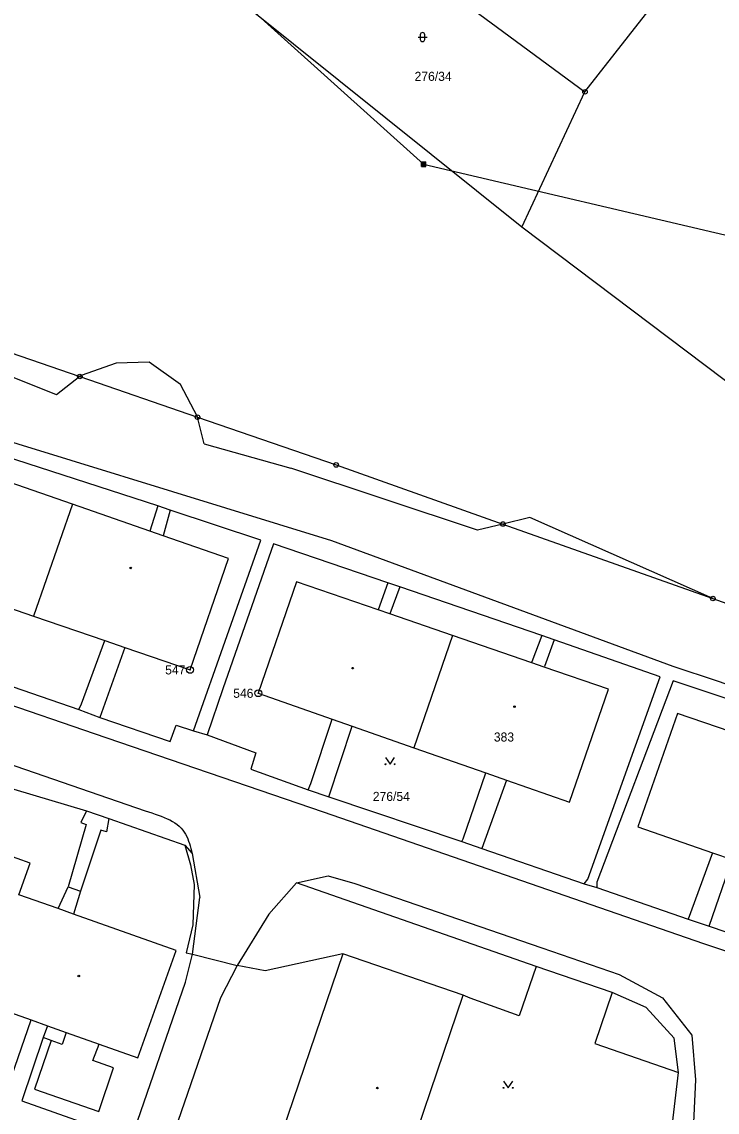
# Model space of a CAD drawing. Extents: x -745926 to -742978, y -968282 to -965689.
# Drawn here: x -744726.5 to -744649.7, y -967027 to -966906.6 of the extents above; entities that cross this region are included whole.
import ezdxf

# ---------------------------------------------------------------- set-up
doc = ezdxf.new("R2010")
doc.units = 0
for name, color, linetype in [('Hranice parcel', 7, 'Continuous'), ('Parcelní čísla', 7, 'Continuous'), ('Poz předměty', 7, 'Continuous'), ('Vnitřní kresba', 7, 'Continuous'), ('Značky bodu BP', 7, 'Continuous'), ('Značky budov', 7, 'Continuous'), ('Značky kultur', 7, 'Continuous')]:
    doc.layers.add(name, color=color, linetype=linetype)

msp = doc.modelspace()

# ---------------------------------------------------------------- linework, layer by layer
at = {"layer": 'Hranice parcel'}
for p, q in [((-744664.34, -966914.34), (-744608.93, -966843.39)), ((-744671.3, -966929.27), (-744664.34, -966914.34)), ((-744635.36, -966956.43), (-744671.3, -966929.27)), ((-744707.55, -966984.87), (-744706.03, -966985.33)), ((-744664.43, -967001.78), (-744663.03, -967002.19)), ((-744707.68, -967009.55), (-744702.72, -967010.81))]:
    msp.add_line(p, q, dxfattribs=at)
for points in [[(-744627.78, -966987.01), (-744649.71, -966979.39), (-744654.61, -966977.79), (-744692.27, -966963.9), (-744738.66, -966949.62), (-744739.71, -966948.97), (-744740.38, -966948.96), (-744778.84, -966930.46), (-744815.82, -966899.53), (-744818.58, -966883.89), (-744822.45, -966860.57), (-744822.45, -966858.85), (-744822.42, -966856.77), (-744822.4, -966854.94), (-744822.37, -966853.08), (-744822.37, -966851.59), (-744822.35, -966814.99), (-744823.48, -966815.03), (-744822.59, -966803.93), (-744824.77, -966768.68), (-744832.65, -966757.45)], [(-744671.3, -966929.27), (-744781.98, -966840.55), (-744773.37, -966830.03)], [(-744773.37, -966830.03), (-744770.39, -966832.47), (-744703.2, -966887.58), (-744695.37, -966891.46), (-744664.34, -966914.34)], [(-744812.79, -966854.17), (-744813.4, -966862.64), (-744813.73, -966867.2), (-744808, -966902.66), (-744776.73, -966926.26), (-744745.23, -966937.12), (-744720.11, -966945.77), (-744707.11, -966950.26), (-744691.81, -966955.53), (-744673.4, -966962.06), (-744650.22, -966970.28), (-744647.24, -966971.34)], [(-744707.55, -966984.87), (-744700.13, -966963.82), (-744710.14, -966960.53), (-744711.51, -966960.06), (-744727.15, -966954.96), (-744728.44, -966954.54), (-744739.28, -966950.98), (-744745.85, -966967), (-744748.26, -966972.98)], [(-744732.08, -966969.87), (-744725.21, -966972.23), (-744717.35, -966974.93), (-744715.13, -966975.69), (-744707.94, -966978.16), (-744703.71, -966965.87), (-744710.92, -966963.35), (-744712.38, -966962.84), (-744720.91, -966959.86), (-744727.9, -966957.42), (-744729.3, -966956.93), (-744738.11, -966953.85), (-744742.47, -966966.3), (-744734.37, -966969.08), (-744732.08, -966969.87)], [(-744664.43, -967001.78), (-744664.04, -967001.28), (-744656.03, -966978.91), (-744667.73, -966974.83), (-744669.12, -966974.37), (-744684.78, -966968.98), (-744686.09, -966968.53), (-744698.73, -966964.26), (-744704.32, -966980.26), (-744706.03, -966985.33)], [(-744700.4, -966980.74), (-744692.25, -966983.59), (-744690.05, -966984.36), (-744683.22, -966986.75), (-744675.28, -966989.54), (-744672.99, -966990.34), (-744666.04, -966992.77), (-744661.74, -966980.29), (-744668.84, -966977.85), (-744670.22, -966977.37), (-744678.96, -966974.36), (-744685.89, -966971.98), (-744687.16, -966971.54), (-744696.18, -966968.43), (-744700.4, -966980.74)], [(-744784.3, -966971.12), (-744752.54, -966982.26), (-744750.13, -966983.09), (-744736.11, -966988.32), (-744727.4, -966991.33), (-744719.35, -966993.73), (-744716.91, -966994.58), (-744708.53, -966997.5), (-744707.88, -966999.67), (-744707.48, -967001.85), (-744707.64, -967006.3), (-744708.35, -967009.41), (-744707.68, -967009.55)], [(-744748.26, -966972.98), (-744737.18, -966976.65), (-744734.84, -966977.5), (-744720.2, -966982.53), (-744717.89, -966983.4), (-744710.13, -966986.07), (-744709.48, -966984.27), (-744707.55, -966984.87)], [(-744624.63, -966989.55), (-744625.82, -966989.13), (-744627.17, -966988.69), (-744642.96, -966983.23), (-744644.23, -966982.84), (-744654.6, -966979.36), (-744663.03, -967001.61), (-744663.03, -967002.19)], [(-744641.26, -967001.49), (-744633.32, -967004.25), (-744631.15, -967005.01), (-744624.08, -967007.47), (-744619.61, -966994.77), (-744626.9, -966992.28), (-744628.31, -966991.8), (-744636.87, -966988.88), (-744643.88, -966986.49), (-744645.31, -966986), (-744654.14, -966982.99), (-744658.49, -966995.48), (-744650.28, -966998.34), (-744648.11, -966999.1), (-744641.26, -967001.49)], [(-744706.03, -966985.33), (-744700.69, -966987.33), (-744701.21, -966989.11), (-744694.89, -966991.39), (-744692.6, -966992.17), (-744677.94, -966997.1), (-744675.71, -966997.87), (-744664.43, -967001.78)], [(-744720.79, -967005.12), (-744722.5, -967004.51), (-744726.82, -967002.98), (-744725.58, -966999.49), (-744729.94, -966997.94)], [(-744625.84, -967057.82), (-744626.36, -967056.75), (-744626.56, -967053.84), (-744628.6, -967052.05), (-744630.08, -967051.55), (-744645.48, -967046.06), (-744651.12, -967042.4), (-744654.67, -967036.55), (-744655.31, -967033.56), (-744654.02, -967022.62), (-744654.48, -967018.82), (-744657.58, -967015.44), (-744661.33, -967013.77), (-744669.74, -967010.9), (-744696.2, -967001.68), (-744699.25, -967005.14), (-744702.72, -967010.81)], [(-744663.03, -967002.19), (-744652.96, -967005.68), (-744650.65, -967006.45), (-744635.93, -967011.45), (-744633.62, -967012.26), (-744631.06, -967013.64), (-744629.91, -967012.13), (-744626.8, -967014.59)], [(-744731.04, -967014.83), (-744725.48, -967016.81), (-744723.67, -967017.45), (-744721.6, -967018.19), (-744722.06, -967019.52), (-744723.26, -967019.07), (-744725.11, -967024.46), (-744718.01, -967026.9), (-744716.4, -967022.09), (-744718.65, -967021.3), (-744717.98, -967019.48), (-744713.7, -967021), (-744709.48, -967009.14), (-744720.79, -967005.12)], [(-744732.33, -967067.52), (-744726.17, -967065.66), (-744724.21, -967058.13), (-744716.89, -967036), (-744715.63, -967033.27), (-744714.43, -967030), (-744708.43, -967012.63), (-744707.68, -967009.55)], [(-744691.08, -967009.49), (-744698.98, -967032.76), (-744695.35, -967034.03), (-744697.16, -967038.95), (-744703.88, -967036.64), (-744713.79, -967065.36), (-744706.42, -967068.2), (-744712.77, -967086.04), (-744703.58, -967089), (-744701.81, -967089.59), (-744695.24, -967091.66), (-744693.5, -967092.27), (-744696.04, -967099.62), (-744650.43, -967115.72), (-744647.79, -967108.29), (-744643.49, -967109.92)], [(-744691.08, -967009.49), (-744699.66, -967011.38), (-744702.72, -967010.81)], [(-744625.84, -967057.82), (-744627.66, -967057.26), (-744630.07, -967056.33), (-744631.47, -967055.72), (-744647.96, -967050.01), (-744652.67, -967063.77), (-744662.77, -967060.57), (-744658.02, -967047.43), (-744671.18, -967042.61), (-744675.78, -967041.06), (-744677.43, -967045.75), (-744682.33, -967060.09), (-744691.59, -967054.68), (-744687.36, -967042.31), (-744688.22, -967042.01), (-744686.56, -967037.11), (-744685.7, -967037.41), (-744677.79, -967014.07), (-744691.08, -967009.49)], [(-744702.72, -967010.81), (-744704.58, -967014.37), (-744720.18, -967059.59), (-744722.02, -967065.75), (-744721.47, -967072.64), (-744717.1, -967081.95), (-744707.96, -967096.22), (-744700.48, -967104.95), (-744692.45, -967111.29), (-744683.59, -967116.31), (-744671.48, -967120.93), (-744660.56, -967122.15), (-744652.94, -967119.57), (-744647.9, -967115.77), (-744643.49, -967109.92)]]:
    msp.add_lwpolyline(points, dxfattribs=at)
at = {"layer": 'Poz předměty'}
for p, q in [((-744720.49, -966887.82), (-744682.15, -966922.33)), ((-744682.4, -966922.08), (-744681.9, -966922.08)), ((-744682.4, -966922.58), (-744682.4, -966922.08)), ((-744682.4, -966922.18), (-744681.9, -966922.18)), ((-744682.4, -966922.28), (-744681.9, -966922.28)), ((-744682.4, -966922.38), (-744681.9, -966922.38)), ((-744682.4, -966922.48), (-744681.9, -966922.48)), ((-744682.3, -966922.58), (-744682.3, -966922.08)), ((-744682.2, -966922.58), (-744682.2, -966922.08)), ((-744682.15, -966922.33), (-744620.04, -966936.89)), ((-744682.1, -966922.58), (-744682.1, -966922.08)), ((-744682, -966922.58), (-744682, -966922.08)), ((-744681.9, -966922.58), (-744681.9, -966922.08)), ((-744682.4, -966922.58), (-744681.9, -966922.58))]:
    msp.add_line(p, q, dxfattribs=at)
at = {"layer": 'Vnitřní kresba'}
for p, q in [((-744722.67, -966947.78), (-744738.76, -966941.42)), ((-744716.11, -966944.3), (-744719.97, -966945.66)), ((-744712.45, -966944.18), (-744716.11, -966944.3)), ((-744708.98, -966946.64), (-744712.45, -966944.18)), ((-744720.11, -966945.77), (-744722.67, -966947.78)), ((-744719.97, -966945.66), (-744720.11, -966945.77)), ((-744707.12, -966950.21), (-744708.98, -966946.64)), ((-744707.11, -966950.26), (-744707.12, -966950.21)), ((-744706.37, -966953.2), (-744707.11, -966950.26)), ((-744706.37, -966953.2), (-744696.8, -966955.88)), ((-744676.2, -966962.75), (-744696.8, -966955.88)), ((-744720.91, -966959.86), (-744725.21, -966972.23)), ((-744711.51, -966960.06), (-744712.38, -966962.84)), ((-744710.14, -966960.53), (-744710.92, -966963.35)), ((-744673.4, -966962.06), (-744676.2, -966962.75)), ((-744670.41, -966961.33), (-744673.4, -966962.06)), ((-744650.22, -966970.28), (-744670.41, -966961.33)), ((-744686.09, -966968.53), (-744687.16, -966971.54)), ((-744684.78, -966968.98), (-744685.89, -966971.98)), ((-744719.92, -966981.91), (-744717.35, -966974.93)), ((-744678.96, -966974.36), (-744683.22, -966986.75)), ((-744669.12, -966974.37), (-744670.19, -966977.27)), ((-744667.73, -966974.83), (-744668.82, -966977.79)), ((-744715.13, -966975.69), (-744717.89, -966983.4)), ((-744670.22, -966977.37), (-744670.19, -966977.27)), ((-744668.84, -966977.85), (-744668.82, -966977.79)), ((-744718.5, -966985.23), (-744735.4, -966979.39)), ((-744720.2, -966982.53), (-744719.92, -966981.91)), ((-744694.6, -966990.72), (-744692.25, -966983.59)), ((-744692.6, -966992.17), (-744690.05, -966984.36)), ((-744693.19, -966993.88), (-744718.5, -966985.23)), ((-744733.16, -966986.72), (-744712.88, -966993.72)), ((-744677.79, -966996.8), (-744675.28, -966989.54)), ((-744694.89, -966991.39), (-744694.6, -966990.72)), ((-744672.99, -966990.34), (-744675.71, -966997.87)), ((-744719.35, -966993.73), (-744719.99, -966995.02)), ((-744716.91, -966994.58), (-744717.15, -966996.04)), ((-744651.22, -967008.4), (-744693.19, -966993.88)), ((-744719.41, -966995.24), (-744721.38, -967002.1)), ((-744717.78, -966995.86), (-744720.04, -967002.6)), ((-744719.99, -966995.02), (-744719.41, -966995.24)), ((-744717.15, -966996.04), (-744717.78, -966995.86)), ((-744677.94, -966997.1), (-744677.79, -966996.8)), ((-744708.53, -966997.5), (-744707.7, -966998.42)), ((-744707.7, -966998.42), (-744706.87, -967003.27)), ((-744650.28, -966998.34), (-744652.96, -967005.68)), ((-744650.65, -967006.45), (-744648.11, -966999.1)), ((-744696.2, -967001.68), (-744692.69, -967000.91)), ((-744692.69, -967000.91), (-744689.74, -967001.76)), ((-744689.74, -967001.76), (-744669.1, -967008.86)), ((-744722.5, -967004.51), (-744721.38, -967002.1)), ((-744721.38, -967002.1), (-744720.04, -967002.6)), ((-744720.04, -967002.6), (-744720.79, -967005.12)), ((-744707.68, -967009.55), (-744706.87, -967003.27)), ((-744669.1, -967008.86), (-744660.57, -967011.8)), ((-744635.42, -967013.69), (-744651.22, -967008.4)), ((-744669.74, -967010.9), (-744671.6, -967016.37)), ((-744660.57, -967011.8), (-744655.79, -967014.36)), ((-744661.33, -967013.77), (-744663.24, -967019.4)), ((-744677, -967014.39), (-744677.79, -967014.07)), ((-744671.6, -967016.37), (-744677, -967014.39)), ((-744655.79, -967014.36), (-744652.56, -967018.5)), ((-744728.35, -967025.12), (-744725.48, -967016.81)), ((-744723.67, -967017.45), (-744724.16, -967018.76)), ((-744724.16, -967018.76), (-744726.49, -967025.72)), ((-744723.26, -967019.07), (-744724.16, -967018.76)), ((-744721.6, -967018.19), (-744717.98, -967019.48)), ((-744652.56, -967018.5), (-744652.15, -967023.42)), ((-744663.24, -967019.4), (-744654.02, -967022.62)), ((-744652.15, -967023.42), (-744652.71, -967035.77)), ((-744726.49, -967025.72), (-744714.43, -967030))]:
    msp.add_line(p, q, dxfattribs=at)
msp.add_lwpolyline([(-744712.88, -966993.72), (-744712.52, -966993.83), (-744712.16, -966993.95), (-744711.8, -966994.07), (-744711.45, -966994.19), (-744711.11, -966994.32), (-744710.78, -966994.45), (-744710.46, -966994.59), (-744710.16, -966994.73), (-744709.87, -966994.89), (-744709.6, -966995.05), (-744709.35, -966995.23), (-744709.12, -966995.42), (-744708.92, -966995.62), (-744708.73, -966995.84), (-744708.57, -966996.06), (-744708.43, -966996.3), (-744708.3, -966996.55), (-744708.19, -966996.8), (-744708.09, -966997.06), (-744708, -966997.33), (-744707.92, -966997.59), (-744707.84, -966997.87), (-744707.77, -966998.14), (-744707.7, -966998.42)], dxfattribs=at)
at = {"layer": 'Značky bodu BP'}
for centre, radius in [((-744664.34, -966914.34), 0.25), ((-744664.34, -966914.34), 0.0152), ((-744720.11, -966945.77), 0.25), ((-744720.11, -966945.77), 0.0152), ((-744707.11, -966950.26), 0.25), ((-744707.11, -966950.26), 0.0152), ((-744691.81, -966955.53), 0.25), ((-744691.81, -966955.53), 0.0152), ((-744673.4, -966962.06), 0.25), ((-744673.4, -966962.06), 0.0152), ((-744650.22, -966970.28), 0.25), ((-744650.22, -966970.28), 0.0152), ((-744707.94, -966978.16), 0.375), ((-744707.94, -966978.16), 0.015), ((-744700.4, -966980.74), 0.375), ((-744700.4, -966980.74), 0.015)]:
    msp.add_circle(centre, radius, dxfattribs=at)
at = {"layer": 'Značky budov'}
for centre in [(-744714.49, -966966.91), (-744689.99, -966977.97), (-744672.12, -966982.22), (-744720.22, -967011.96), (-744687.26, -967024.32)]:
    msp.add_circle(centre, 0.0875, dxfattribs=at)
at = {"layer": 'Značky kultur'}
for p, q in [((-744682.77, -966908.3), (-744681.77, -966908.3)), ((-744682.52, -966908.05), (-744682.52, -966908.55)), ((-744682.02, -966908.55), (-744682.02, -966908.05))]:
    msp.add_line(p, q, dxfattribs=at)
for points in [[(-744686.35, -966987.83), (-744685.85, -966988.58), (-744685.35, -966987.83)], [(-744673.32, -967023.55), (-744672.82, -967024.3), (-744672.32, -967023.55)]]:
    msp.add_lwpolyline(points, dxfattribs=at)
for centre in [(-744686.35, -966988.58), (-744685.35, -966988.58), (-744673.32, -967024.3), (-744672.32, -967024.3)]:
    msp.add_circle(centre, 0.05, dxfattribs=at)
for centre, start, end in [((-744682.27, -966908.05), 0, 180), ((-744682.27, -966908.55), 180, 359.9879)]:
    msp.add_arc(centre, 0.25, start, end, dxfattribs=at)

# ---------------------------------------------------------------- texts
at = {"layer": 'Parcelní čísla'}
for s, p in [('276/34', (-744683.15, -966913.13)), ('383', (-744674.4, -966986.07)), ('276/54', (-744687.76, -966992.63))]:
    msp.add_text(s, height=1, dxfattribs=at).set_placement(p)
at = {"layer": 'Značky bodu BP'}
for s, p in [('547', (-744710.68, -966978.66)), ('546', (-744703.17, -966981.24))]:
    msp.add_text(s, height=1, dxfattribs=at).set_placement(p)

doc.saveas('drawing.dxf')
